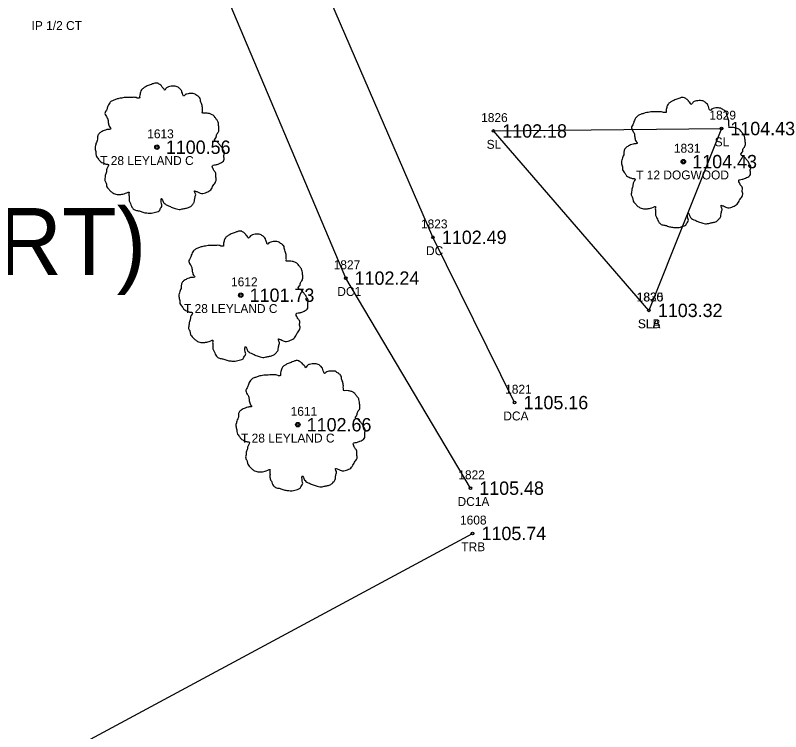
# Model space of a CAD drawing. Extents: x 1539151 to 1541799, y 1198646 to 1201165.
# Drawn here: x 1541070.5 to 1541156.3, y 1200262.8 to 1200343.1 of the extents above; entities that cross this region are included whole.
import ezdxf

# ---------------------------------------------------------------- set-up
doc = ezdxf.new("R2010")
doc.units = 0
for name, color, linetype in [('RD_EX_Conc', 7, 'Continuous'), ('RD_EX_Conc_txCode', 7, 'Continuous'), ('RD_EX_DV_Prop_txCode', 7, 'Continuous'), ('RD_EX_TX_Conc_ELEV', 7, 'Continuous'), ('RD_EX_TX_VEG_ELEV', 7, 'Continuous'), ('RD_EX_VEG', 7, 'Continuous'), ('RD_EX_VEG_txCode', 7, 'Continuous'), ('RD_HC_Cl', 7, 'Continuous'), ('RD_HC_Data', 7, 'Continuous'), ('RD_SMD_Locator', 7, 'Continuous')]:
    doc.layers.add(name, color=color, linetype=linetype)

msp = doc.modelspace()

# ---------------------------------------------------------------- linework, layer by layer
at = {"layer": 'RD_EX_Conc'}
for points in [[(1541126.431, 1200299.676), (1541117.278, 1200318.219), (1541103.059, 1200351.109)], [(1541121.467, 1200290.074), (1541107.496, 1200313.64), (1541093.435, 1200347.016)]]:
    msp.add_lwpolyline(points, dxfattribs=at)
at = {"layer": 'RD_EX_VEG'}
for points in [[(1541141.488, 1200310.021), (1541124.048, 1200330.149), (1541149.616, 1200330.425), (1541141.488, 1200310.021)], [(1540970.036, 1200190.253), (1540931.471, 1200242.982), (1540974.477, 1200278.355), (1541008.822, 1200224.186), (1541121.721, 1200284.998)]]:
    msp.add_lwpolyline(points, dxfattribs=at)
for centre, radius in [((1541086.333, 1200328.329), 0.25), ((1541086.321, 1200328.31), 0.0001), ((1541145.349, 1200326.712), 0.25), ((1541145.336, 1200326.693), 0.0001), ((1541095.731, 1200311.724), 0.25), ((1541095.719, 1200311.705), 0.0001), ((1541102.126, 1200297.195), 0.25), ((1541102.114, 1200297.176), 0.0001)]:
    msp.add_circle(centre, radius, dxfattribs=at)
for points in [[(1541086.465, 1200335.496), (1541086.165, 1200335.521), (1541085.841, 1200335.421), (1541085.591, 1200335.321), (1541085.366, 1200335.246), (1541085.141, 1200335.146), (1541084.841, 1200334.971), (1541084.616, 1200334.772), (1541084.491, 1200334.522), (1541084.441, 1200334.297), (1541084.391, 1200334.022), (1541084.391, 1200333.847), (1541084.266, 1200333.822), (1541084.116, 1200333.847), (1541083.866, 1200333.922), (1541083.617, 1200333.922), (1541083.367, 1200333.922), (1541083.017, 1200333.897), (1541082.667, 1200333.897), (1541082.392, 1200333.847), (1541082.067, 1200333.797), (1541081.692, 1200333.672), (1541081.343, 1200333.547), (1541081.043, 1200333.297), (1541080.793, 1200332.822), (1541080.668, 1200332.473), (1541080.518, 1200332.223), (1541080.668, 1200331.773), (1541080.843, 1200331.423), (1541080.868, 1200331.223), (1541080.943, 1200330.798), (1541081.043, 1200330.573), (1541081.168, 1200330.373), (1541081.093, 1200330.349), (1541080.718, 1200330.299), (1541080.418, 1200330.199), (1541079.993, 1200329.974), (1541079.768, 1200329.749), (1541079.668, 1200329.424), (1541079.643, 1200329.074), (1541079.543, 1200328.874), (1541079.468, 1200328.599), (1541079.443, 1200328.524), (1541079.393, 1200328.199), (1541079.493, 1200327.75), (1541079.518, 1200327.4), (1541079.643, 1200327.175), (1541079.793, 1200327), (1541079.968, 1200326.75), (1541080.368, 1200326.525), (1541080.693, 1200326.425), (1541080.893, 1200326.4), (1541080.718, 1200325.9), (1541080.668, 1200325.551), (1541080.543, 1200325.151), (1541080.543, 1200325.076), (1541080.493, 1200324.601), (1541080.643, 1200324.276), (1541080.718, 1200323.901), (1541080.893, 1200323.676), (1541081.168, 1200323.377), (1541081.492, 1200323.152), (1541081.992, 1200323.027), (1541082.392, 1200323.052), (1541082.967, 1200323.227), (1541083.217, 1200323.302), (1541083.192, 1200323.127), (1541083.217, 1200322.752), (1541083.217, 1200322.327), (1541083.367, 1200322.002), (1541083.467, 1200321.727), (1541083.617, 1200321.477), (1541083.941, 1200321.252), (1541084.341, 1200321.177), (1541084.766, 1200321.028), (1541085.216, 1200320.953), (1541085.716, 1200320.928), (1541086.315, 1200321.077), (1541086.59, 1200321.202), (1541086.69, 1200321.377), (1541086.89, 1200321.752), (1541086.84, 1200321.977), (1541086.865, 1200322.577), (1541086.965, 1200322.402), (1541087.14, 1200322.052), (1541087.64, 1200321.752), (1541088.04, 1200321.577), (1541088.514, 1200321.427), (1541088.814, 1200321.352), (1541089.289, 1200321.427), (1541089.664, 1200321.502), (1541090.039, 1200321.627), (1541090.339, 1200321.902), (1541090.514, 1200322.177), (1541090.564, 1200322.452), (1541090.638, 1200322.827), (1541090.688, 1200323.002)], [(1541090.688, 1200323.002), (1541090.614, 1200323.177), (1541090.564, 1200323.427), (1541090.638, 1200323.401), (1541090.813, 1200323.352), (1541091.088, 1200323.227), (1541091.313, 1200323.152), (1541091.638, 1200323.177), (1541091.913, 1200323.277), (1541092.363, 1200323.552), (1541092.638, 1200324.026), (1541092.912, 1200324.426), (1541092.987, 1200324.751), (1541092.937, 1200324.976), (1541092.912, 1200325.476), (1541092.713, 1200325.725), (1541092.663, 1200325.85), (1541092.563, 1200326.25), (1541092.638, 1200326.3), (1541092.912, 1200326.35), (1541093.287, 1200326.475), (1541093.562, 1200326.6), (1541093.787, 1200326.775), (1541093.862, 1200327), (1541093.837, 1200327.4), (1541093.887, 1200327.8), (1541093.812, 1200327.95), (1541093.712, 1200328.099), (1541093.637, 1200328.299), (1541093.487, 1200328.449), (1541093.387, 1200328.599), (1541093.287, 1200328.699), (1541093.162, 1200328.849), (1541092.987, 1200328.974), (1541092.838, 1200329.024), (1541092.788, 1200329.174), (1541092.937, 1200329.374), (1541092.987, 1200329.474), (1541093.012, 1200329.699), (1541093.237, 1200330.049), (1541093.287, 1200330.448), (1541093.237, 1200330.873), (1541093.187, 1200331.148), (1541093.037, 1200331.423), (1541092.838, 1200331.673), (1541092.713, 1200331.848), (1541092.538, 1200331.973), (1541092.213, 1200332.098), (1541091.963, 1200332.148), (1541091.613, 1200332.148), (1541091.413, 1200332.198), (1541091.438, 1200332.248), (1541091.438, 1200332.398), (1541091.438, 1200332.673), (1541091.363, 1200333.122), (1541091.213, 1200333.622), (1541091.213, 1200333.647), (1541091.113, 1200333.897), (1541090.888, 1200334.097), (1541090.713, 1200334.197), (1541090.514, 1200334.322), (1541090.264, 1200334.347), (1541089.964, 1200334.347), (1541089.689, 1200334.297), (1541089.489, 1200334.197), (1541089.314, 1200334.072), (1541089.239, 1200334.222), (1541089.139, 1200334.522), (1541089.089, 1200334.672), (1541088.939, 1200334.846), (1541088.714, 1200335.046), (1541088.264, 1200335.171), (1541087.64, 1200335.096), (1541087.34, 1200334.897), (1541087.19, 1200334.722), (1541087.14, 1200334.846), (1541086.94, 1200335.046), (1541086.84, 1200335.221), (1541086.665, 1200335.346), (1541086.515, 1200335.446), (1541086.415, 1200335.496)], [(1541145.481, 1200333.879), (1541145.181, 1200333.904), (1541144.856, 1200333.804), (1541144.606, 1200333.704), (1541144.381, 1200333.629), (1541144.156, 1200333.529), (1541143.856, 1200333.354), (1541143.631, 1200333.154), (1541143.506, 1200332.904), (1541143.456, 1200332.679), (1541143.407, 1200332.405), (1541143.407, 1200332.23), (1541143.282, 1200332.205), (1541143.132, 1200332.23), (1541142.882, 1200332.305), (1541142.632, 1200332.305), (1541142.382, 1200332.305), (1541142.032, 1200332.28), (1541141.682, 1200332.28), (1541141.407, 1200332.23), (1541141.083, 1200332.18), (1541140.708, 1200332.055), (1541140.358, 1200331.93), (1541140.058, 1200331.68), (1541139.808, 1200331.205), (1541139.683, 1200330.855), (1541139.533, 1200330.605), (1541139.683, 1200330.156), (1541139.858, 1200329.806), (1541139.883, 1200329.606), (1541139.958, 1200329.181), (1541140.058, 1200328.956), (1541140.183, 1200328.756), (1541140.108, 1200328.731), (1541139.733, 1200328.681), (1541139.433, 1200328.581), (1541139.008, 1200328.356), (1541138.784, 1200328.131), (1541138.684, 1200327.806), (1541138.659, 1200327.457), (1541138.559, 1200327.257), (1541138.484, 1200326.982), (1541138.459, 1200326.907), (1541138.409, 1200326.582), (1541138.509, 1200326.132), (1541138.534, 1200325.782), (1541138.659, 1200325.557), (1541138.809, 1200325.383), (1541138.983, 1200325.133), (1541139.383, 1200324.908), (1541139.708, 1200324.808), (1541139.908, 1200324.783), (1541139.733, 1200324.283), (1541139.683, 1200323.933), (1541139.558, 1200323.533), (1541139.558, 1200323.458), (1541139.508, 1200322.984), (1541139.658, 1200322.659), (1541139.733, 1200322.284), (1541139.908, 1200322.059), (1541140.183, 1200321.759), (1541140.508, 1200321.534), (1541141.008, 1200321.409), (1541141.407, 1200321.434), (1541141.982, 1200321.609), (1541142.232, 1200321.684), (1541142.207, 1200321.509), (1541142.232, 1200321.134), (1541142.232, 1200320.71), (1541142.382, 1200320.385), (1541142.482, 1200320.11), (1541142.632, 1200319.86), (1541142.957, 1200319.635), (1541143.357, 1200319.56), (1541143.781, 1200319.41), (1541144.231, 1200319.335), (1541144.731, 1200319.31), (1541145.331, 1200319.46), (1541145.606, 1200319.585), (1541145.706, 1200319.76), (1541145.905, 1200320.135), (1541145.855, 1200320.36), (1541145.88, 1200320.96), (1541145.98, 1200320.785), (1541146.155, 1200320.435), (1541146.655, 1200320.135), (1541147.055, 1200319.96), (1541147.53, 1200319.81), (1541147.83, 1200319.735), (1541148.304, 1200319.81), (1541148.679, 1200319.885), (1541149.054, 1200320.01), (1541149.354, 1200320.285), (1541149.529, 1200320.56), (1541149.579, 1200320.835), (1541149.654, 1200321.209), (1541149.704, 1200321.384)], [(1541149.704, 1200321.384), (1541149.629, 1200321.559), (1541149.579, 1200321.809), (1541149.654, 1200321.784), (1541149.829, 1200321.734), (1541150.104, 1200321.609), (1541150.329, 1200321.534), (1541150.653, 1200321.559), (1541150.928, 1200321.659), (1541151.378, 1200321.934), (1541151.653, 1200322.409), (1541151.928, 1200322.809), (1541152.003, 1200323.134), (1541151.953, 1200323.358), (1541151.928, 1200323.858), (1541151.728, 1200324.108), (1541151.678, 1200324.233), (1541151.578, 1200324.633), (1541151.653, 1200324.683), (1541151.928, 1200324.733), (1541152.303, 1200324.858), (1541152.578, 1200324.983), (1541152.802, 1200325.158), (1541152.877, 1200325.383), (1541152.852, 1200325.782), (1541152.902, 1200326.182), (1541152.827, 1200326.332), (1541152.727, 1200326.482), (1541152.652, 1200326.682), (1541152.503, 1200326.832), (1541152.403, 1200326.982), (1541152.303, 1200327.082), (1541152.178, 1200327.232), (1541152.003, 1200327.357), (1541151.853, 1200327.407), (1541151.803, 1200327.557), (1541151.953, 1200327.757), (1541152.003, 1200327.856), (1541152.028, 1200328.081), (1541152.253, 1200328.431), (1541152.303, 1200328.831), (1541152.253, 1200329.256), (1541152.203, 1200329.531), (1541152.053, 1200329.806), (1541151.853, 1200330.056), (1541151.728, 1200330.23), (1541151.553, 1200330.355), (1541151.228, 1200330.48), (1541150.978, 1200330.53), (1541150.628, 1200330.53), (1541150.428, 1200330.58), (1541150.453, 1200330.63), (1541150.453, 1200330.78), (1541150.453, 1200331.055), (1541150.378, 1200331.505), (1541150.229, 1200332.005), (1541150.229, 1200332.03), (1541150.129, 1200332.28), (1541149.904, 1200332.479), (1541149.729, 1200332.579), (1541149.529, 1200332.704), (1541149.279, 1200332.729), (1541148.979, 1200332.729), (1541148.704, 1200332.679), (1541148.504, 1200332.579), (1541148.329, 1200332.454), (1541148.254, 1200332.604), (1541148.154, 1200332.904), (1541148.104, 1200333.054), (1541147.955, 1200333.229), (1541147.73, 1200333.429), (1541147.28, 1200333.554), (1541146.655, 1200333.479), (1541146.355, 1200333.279), (1541146.205, 1200333.104), (1541146.155, 1200333.229), (1541145.955, 1200333.429), (1541145.855, 1200333.604), (1541145.681, 1200333.729), (1541145.531, 1200333.829), (1541145.431, 1200333.879)], [(1541095.863, 1200318.891), (1541095.563, 1200318.916), (1541095.239, 1200318.816), (1541094.989, 1200318.716), (1541094.764, 1200318.641), (1541094.539, 1200318.541), (1541094.239, 1200318.366), (1541094.014, 1200318.166), (1541093.889, 1200317.917), (1541093.839, 1200317.692), (1541093.789, 1200317.417), (1541093.789, 1200317.242), (1541093.664, 1200317.217), (1541093.514, 1200317.242), (1541093.264, 1200317.317), (1541093.014, 1200317.317), (1541092.765, 1200317.317), (1541092.415, 1200317.292), (1541092.065, 1200317.292), (1541091.79, 1200317.242), (1541091.465, 1200317.192), (1541091.09, 1200317.067), (1541090.74, 1200316.942), (1541090.441, 1200316.692), (1541090.191, 1200316.217), (1541090.066, 1200315.867), (1541089.916, 1200315.618), (1541090.066, 1200315.168), (1541090.241, 1200314.818), (1541090.266, 1200314.618), (1541090.341, 1200314.193), (1541090.441, 1200313.968), (1541090.566, 1200313.768), (1541090.491, 1200313.743), (1541090.116, 1200313.693), (1541089.816, 1200313.593), (1541089.391, 1200313.369), (1541089.166, 1200313.144), (1541089.066, 1200312.819), (1541089.041, 1200312.469), (1541088.941, 1200312.269), (1541088.866, 1200311.994), (1541088.841, 1200311.919), (1541088.791, 1200311.594), (1541088.891, 1200311.144), (1541088.916, 1200310.795), (1541089.041, 1200310.57), (1541089.191, 1200310.395), (1541089.366, 1200310.145), (1541089.766, 1200309.92), (1541090.091, 1200309.82), (1541090.291, 1200309.795), (1541090.116, 1200309.295), (1541090.066, 1200308.945), (1541089.941, 1200308.546), (1541089.941, 1200308.471), (1541089.891, 1200307.996), (1541090.041, 1200307.671), (1541090.116, 1200307.296), (1541090.291, 1200307.071), (1541090.566, 1200306.771), (1541090.89, 1200306.547), (1541091.39, 1200306.422), (1541091.79, 1200306.447), (1541092.365, 1200306.621), (1541092.615, 1200306.696), (1541092.59, 1200306.522), (1541092.615, 1200306.147), (1541092.615, 1200305.722), (1541092.765, 1200305.397), (1541092.865, 1200305.122), (1541093.014, 1200304.872), (1541093.339, 1200304.647), (1541093.739, 1200304.572), (1541094.164, 1200304.422), (1541094.614, 1200304.347), (1541095.114, 1200304.322), (1541095.713, 1200304.472), (1541095.988, 1200304.597), (1541096.088, 1200304.772), (1541096.288, 1200305.147), (1541096.238, 1200305.372), (1541096.263, 1200305.972), (1541096.363, 1200305.797), (1541096.538, 1200305.447), (1541097.038, 1200305.147), (1541097.438, 1200304.972), (1541097.912, 1200304.822), (1541098.212, 1200304.747), (1541098.687, 1200304.822), (1541099.062, 1200304.897), (1541099.437, 1200305.022), (1541099.737, 1200305.297), (1541099.911, 1200305.572), (1541099.961, 1200305.847), (1541100.036, 1200306.222), (1541100.086, 1200306.397)], [(1541100.086, 1200306.397), (1541100.011, 1200306.572), (1541099.961, 1200306.821), (1541100.036, 1200306.796), (1541100.211, 1200306.746), (1541100.486, 1200306.621), (1541100.711, 1200306.547), (1541101.036, 1200306.572), (1541101.311, 1200306.671), (1541101.761, 1200306.946), (1541102.036, 1200307.421), (1541102.31, 1200307.821), (1541102.385, 1200308.146), (1541102.335, 1200308.371), (1541102.31, 1200308.87), (1541102.11, 1200309.12), (1541102.06, 1200309.245), (1541101.961, 1200309.645), (1541102.036, 1200309.695), (1541102.31, 1200309.745), (1541102.685, 1200309.87), (1541102.96, 1200309.995), (1541103.185, 1200310.17), (1541103.26, 1200310.395), (1541103.235, 1200310.795), (1541103.285, 1200311.194), (1541103.21, 1200311.344), (1541103.11, 1200311.494), (1541103.035, 1200311.694), (1541102.885, 1200311.844), (1541102.785, 1200311.994), (1541102.685, 1200312.094), (1541102.56, 1200312.244), (1541102.385, 1200312.369), (1541102.235, 1200312.419), (1541102.185, 1200312.569), (1541102.335, 1200312.769), (1541102.385, 1200312.869), (1541102.41, 1200313.094), (1541102.635, 1200313.443), (1541102.685, 1200313.843), (1541102.635, 1200314.268), (1541102.585, 1200314.543), (1541102.435, 1200314.818), (1541102.235, 1200315.068), (1541102.11, 1200315.243), (1541101.936, 1200315.368), (1541101.611, 1200315.493), (1541101.361, 1200315.543), (1541101.011, 1200315.543), (1541100.811, 1200315.593), (1541100.836, 1200315.643), (1541100.836, 1200315.792), (1541100.836, 1200316.067), (1541100.761, 1200316.517), (1541100.611, 1200317.017), (1541100.611, 1200317.042), (1541100.511, 1200317.292), (1541100.286, 1200317.492), (1541100.111, 1200317.592), (1541099.911, 1200317.717), (1541099.662, 1200317.742), (1541099.362, 1200317.742), (1541099.087, 1200317.692), (1541098.887, 1200317.592), (1541098.712, 1200317.467), (1541098.637, 1200317.617), (1541098.537, 1200317.917), (1541098.487, 1200318.066), (1541098.337, 1200318.241), (1541098.112, 1200318.441), (1541097.662, 1200318.566), (1541097.038, 1200318.491), (1541096.738, 1200318.291), (1541096.588, 1200318.116), (1541096.538, 1200318.241), (1541096.338, 1200318.441), (1541096.238, 1200318.616), (1541096.063, 1200318.741), (1541095.913, 1200318.841), (1541095.813, 1200318.891)], [(1541102.258, 1200304.362), (1541101.958, 1200304.387), (1541101.634, 1200304.287), (1541101.384, 1200304.187), (1541101.159, 1200304.112), (1541100.934, 1200304.012), (1541100.634, 1200303.837), (1541100.409, 1200303.637), (1541100.284, 1200303.388), (1541100.234, 1200303.163), (1541100.184, 1200302.888), (1541100.184, 1200302.713), (1541100.059, 1200302.688), (1541099.909, 1200302.713), (1541099.659, 1200302.788), (1541099.409, 1200302.788), (1541099.16, 1200302.788), (1541098.81, 1200302.763), (1541098.46, 1200302.763), (1541098.185, 1200302.713), (1541097.86, 1200302.663), (1541097.485, 1200302.538), (1541097.135, 1200302.413), (1541096.836, 1200302.163), (1541096.586, 1200301.688), (1541096.461, 1200301.338), (1541096.311, 1200301.089), (1541096.461, 1200300.639), (1541096.636, 1200300.289), (1541096.661, 1200300.089), (1541096.736, 1200299.664), (1541096.836, 1200299.439), (1541096.961, 1200299.239), (1541096.886, 1200299.214), (1541096.511, 1200299.164), (1541096.211, 1200299.064), (1541095.786, 1200298.84), (1541095.561, 1200298.615), (1541095.461, 1200298.29), (1541095.436, 1200297.94), (1541095.336, 1200297.74), (1541095.261, 1200297.465), (1541095.236, 1200297.39), (1541095.186, 1200297.065), (1541095.286, 1200296.615), (1541095.311, 1200296.266), (1541095.436, 1200296.041), (1541095.586, 1200295.866), (1541095.761, 1200295.616), (1541096.161, 1200295.391), (1541096.486, 1200295.291), (1541096.686, 1200295.266), (1541096.511, 1200294.766), (1541096.461, 1200294.416), (1541096.336, 1200294.017), (1541096.336, 1200293.942), (1541096.286, 1200293.467), (1541096.436, 1200293.142), (1541096.511, 1200292.767), (1541096.686, 1200292.542), (1541096.961, 1200292.242), (1541097.285, 1200292.018), (1541097.785, 1200291.893), (1541098.185, 1200291.918), (1541098.76, 1200292.092), (1541099.01, 1200292.167), (1541098.985, 1200291.993), (1541099.01, 1200291.618), (1541099.01, 1200291.193), (1541099.16, 1200290.868), (1541099.26, 1200290.593), (1541099.409, 1200290.343), (1541099.734, 1200290.118), (1541100.134, 1200290.043), (1541100.559, 1200289.893), (1541101.009, 1200289.818), (1541101.509, 1200289.793), (1541102.108, 1200289.943), (1541102.383, 1200290.068), (1541102.483, 1200290.243), (1541102.683, 1200290.618), (1541102.633, 1200290.843), (1541102.658, 1200291.443), (1541102.758, 1200291.268), (1541102.933, 1200290.918), (1541103.433, 1200290.618), (1541103.833, 1200290.443), (1541104.307, 1200290.293), (1541104.607, 1200290.218), (1541105.082, 1200290.293), (1541105.457, 1200290.368), (1541105.832, 1200290.493), (1541106.132, 1200290.768), (1541106.306, 1200291.043), (1541106.356, 1200291.318), (1541106.431, 1200291.693), (1541106.481, 1200291.868)], [(1541106.481, 1200291.868), (1541106.406, 1200292.043), (1541106.356, 1200292.292), (1541106.431, 1200292.267), (1541106.606, 1200292.217), (1541106.881, 1200292.092), (1541107.106, 1200292.018), (1541107.431, 1200292.043), (1541107.706, 1200292.142), (1541108.156, 1200292.417), (1541108.431, 1200292.892), (1541108.705, 1200293.292), (1541108.78, 1200293.617), (1541108.73, 1200293.842), (1541108.705, 1200294.341), (1541108.505, 1200294.591), (1541108.455, 1200294.716), (1541108.356, 1200295.116), (1541108.431, 1200295.166), (1541108.705, 1200295.216), (1541109.08, 1200295.341), (1541109.355, 1200295.466), (1541109.58, 1200295.641), (1541109.655, 1200295.866), (1541109.63, 1200296.266), (1541109.68, 1200296.665), (1541109.605, 1200296.815), (1541109.505, 1200296.965), (1541109.43, 1200297.165), (1541109.28, 1200297.315), (1541109.18, 1200297.465), (1541109.08, 1200297.565), (1541108.955, 1200297.715), (1541108.78, 1200297.84), (1541108.63, 1200297.89), (1541108.58, 1200298.04), (1541108.73, 1200298.24), (1541108.78, 1200298.34), (1541108.805, 1200298.565), (1541109.03, 1200298.914), (1541109.08, 1200299.314), (1541109.03, 1200299.739), (1541108.98, 1200300.014), (1541108.83, 1200300.289), (1541108.63, 1200300.539), (1541108.505, 1200300.714), (1541108.331, 1200300.839), (1541108.006, 1200300.964), (1541107.756, 1200301.014), (1541107.406, 1200301.014), (1541107.206, 1200301.064), (1541107.231, 1200301.114), (1541107.231, 1200301.263), (1541107.231, 1200301.538), (1541107.156, 1200301.988), (1541107.006, 1200302.488), (1541107.006, 1200302.513), (1541106.906, 1200302.763), (1541106.681, 1200302.963), (1541106.506, 1200303.063), (1541106.306, 1200303.188), (1541106.057, 1200303.213), (1541105.757, 1200303.213), (1541105.482, 1200303.163), (1541105.282, 1200303.063), (1541105.107, 1200302.938), (1541105.032, 1200303.088), (1541104.932, 1200303.388), (1541104.882, 1200303.537), (1541104.732, 1200303.712), (1541104.507, 1200303.912), (1541104.057, 1200304.037), (1541103.433, 1200303.962), (1541103.133, 1200303.762), (1541102.983, 1200303.587), (1541102.933, 1200303.712), (1541102.733, 1200303.912), (1541102.633, 1200304.087), (1541102.458, 1200304.212), (1541102.308, 1200304.312), (1541102.208, 1200304.362)]]:
    msp.add_spline(points, degree=3, dxfattribs=at)
at = {"layer": 'RD_HC_Cl'}
msp.add_arc((1541347.273, 1199701.685), 731.435, 99.312315, 138.327529, dxfattribs=at)
at = {"layer": 'RD_SMD_Locator'}
for centre in [(1541124.048, 1200330.149), (1541149.616, 1200330.425), (1541086.333, 1200328.329), (1541145.349, 1200326.712), (1541117.278, 1200318.219), (1541107.496, 1200313.64), (1541095.731, 1200311.724), (1541141.488, 1200310.021), (1541141.488, 1200310.021), (1541126.431, 1200299.676), (1541102.126, 1200297.195), (1541121.467, 1200290.074), (1541121.721, 1200284.998)]:
    msp.add_circle(centre, 0.15, dxfattribs=at)

# ---------------------------------------------------------------- texts
at = {"layer": 'RD_EX_Conc_txCode'}
for s, p in [('1823', (1541115.931, 1200319.219)), ('DC', (1541116.498, 1200316.219)), ('1827', (1541106.15, 1200314.64)), ('DC1', (1541106.551, 1200311.64)), ('1821', (1541125.368, 1200300.676)), ('DCA', (1541125.163, 1200297.676)), ('1822', (1541120.12, 1200291.074)), ('DC1A', (1541120.034, 1200288.074))]:
    msp.add_text(s, height=1, dxfattribs=at).set_placement(p)
at = {"layer": 'RD_EX_DV_Prop_txCode'}
msp.add_text('IP 1/2 CT', height=1, dxfattribs=at).set_placement((1541072.282, 1200341.476))
at = {"layer": 'RD_EX_TX_Conc_ELEV'}
for s, p in [('1102.49', (1541118.278, 1200317.469)), ('1102.24', (1541108.496, 1200312.89)), ('1105.16', (1541127.431, 1200298.926)), ('1105.48', (1541122.467, 1200289.324))]:
    msp.add_text(s, height=1.5, dxfattribs=at).set_placement(p)
at = {"layer": 'RD_EX_TX_VEG_ELEV'}
for s, p in [('1102.18', (1541125.048, 1200329.399)), ('1104.43', (1541150.616, 1200329.675)), ('1100.56', (1541087.333, 1200327.579)), ('1104.43', (1541146.349, 1200325.962)), ('1101.73', (1541096.731, 1200310.974)), ('1103.32', (1541142.488, 1200309.271)), ('1103.32', (1541142.488, 1200309.271)), ('1102.66', (1541103.126, 1200296.445)), ('1105.74', (1541122.721, 1200284.248))]:
    msp.add_text(s, height=1.5, dxfattribs=at).set_placement(p)
at = {"layer": 'RD_EX_VEG_txCode'}
for s, p in [('1826', (1541122.678, 1200331.149)), ('1829', (1541148.27, 1200331.425)), ('1613', (1541085.247, 1200329.329)), ('SL', (1541123.292, 1200328.149)), ('SL', (1541148.86, 1200328.425)), ('1831', (1541144.286, 1200327.712)), ('T 28 LEYLAND C', (1541079.971, 1200326.329)), ('T 12 DOGWOOD', (1541140.057, 1200324.712)), ('1612', (1541094.645, 1200312.724)), ('1830', (1541140.103, 1200311.021)), ('1825', (1541140.142, 1200311.021)), ('T 28 LEYLAND C', (1541089.369, 1200309.724)), ('SLA', (1541140.244, 1200308.021)), ('SLB', (1541140.26, 1200308.021)), ('1611', (1541101.323, 1200298.195)), ('T 28 LEYLAND C', (1541095.764, 1200295.195)), ('1608', (1541120.311, 1200285.998)), ('TRB', (1541120.453, 1200282.998))]:
    msp.add_text(s, height=1, dxfattribs=at).set_placement(p)
at = {"layer": 'RD_HC_Data'}
msp.add_text('    = 39%%d 00\' 55" (RT)', height=7.5, dxfattribs=at).set_placement((1540994, 1200314))

doc.saveas('drawing.dxf')
